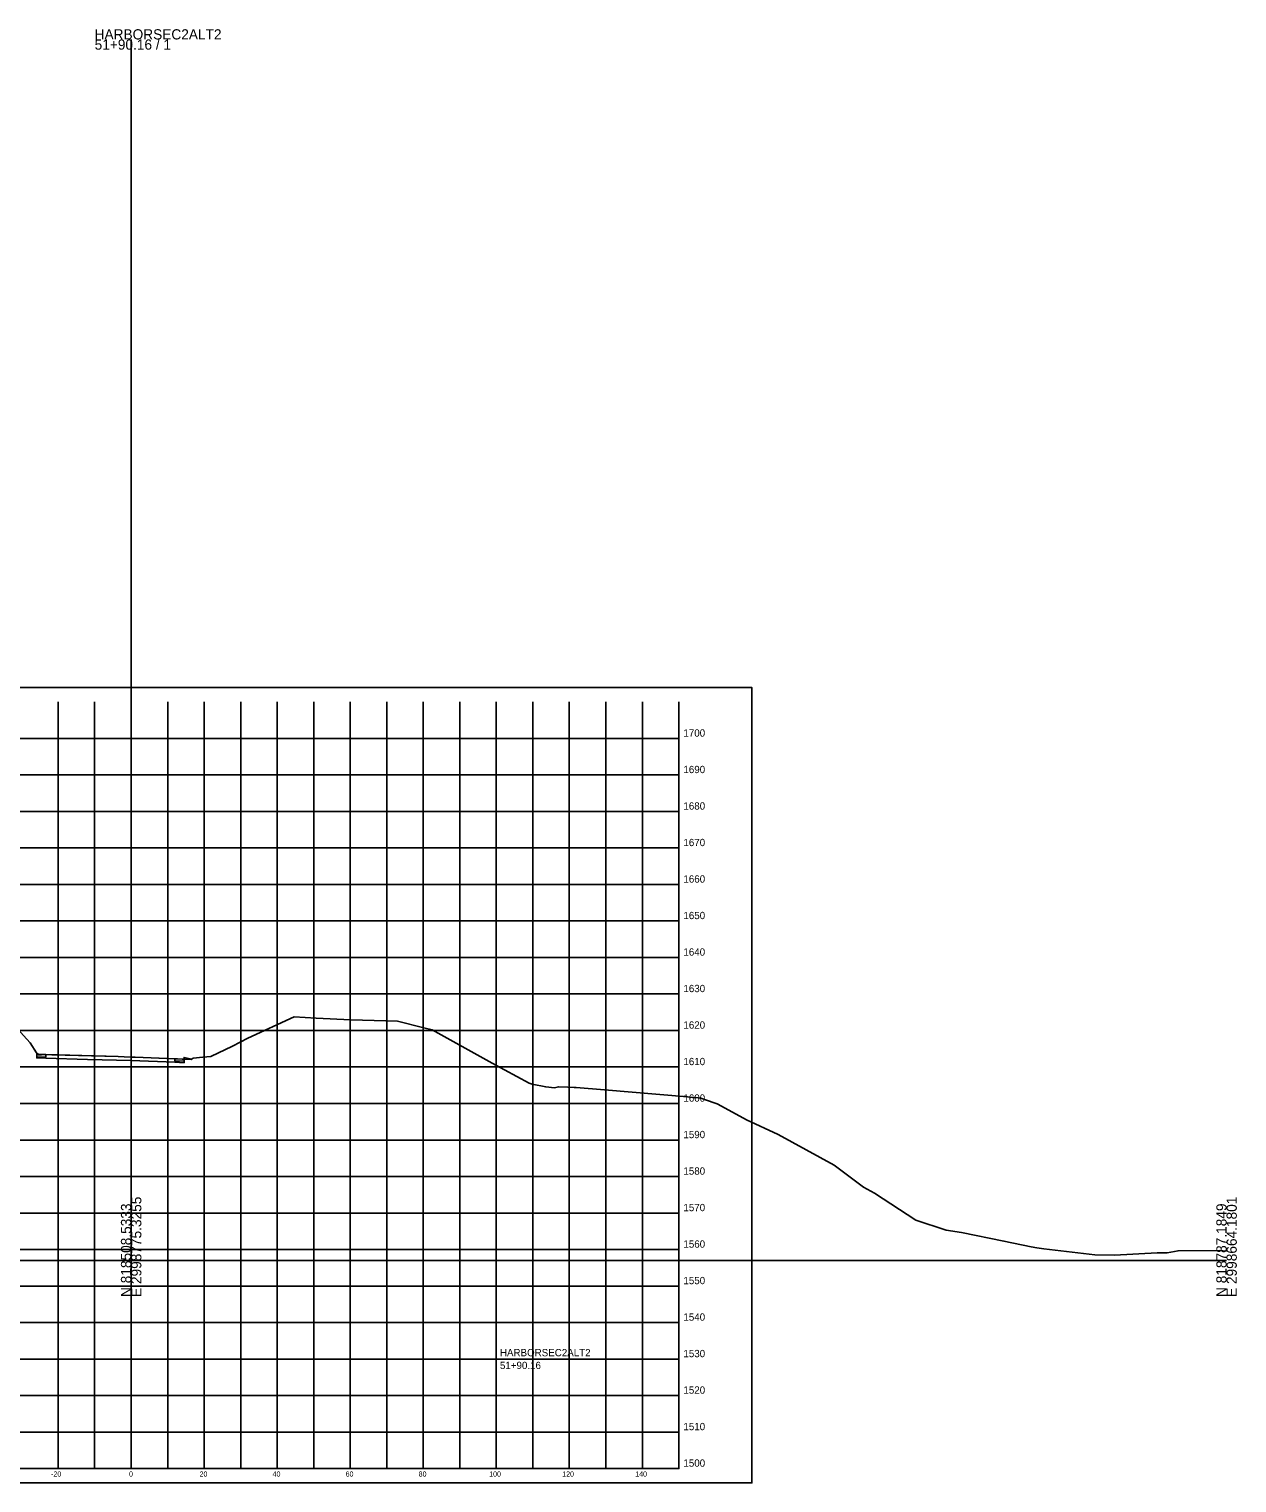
# Model space of a CAD drawing. Extents: x -26 to 1067, y -71 to 1837.
# Drawn here: x 272 to 602.8, y 1439.1 to 1837.3 of the extents above; entities that cross this region are included whole.
import ezdxf

# ---------------------------------------------------------------- set-up
doc = ezdxf.new("R2010")
doc.units = 0
for name, color, linetype in [('DESIGN - EARTHWORK - Shapes', 7, 'Continuous'), ('DESIGN - SHEET - Corner Text', 7, 'Continuous'), ('DESIGN - SHEET - Light Grid', 7, 'Continuous'), ('DESIGN - SHEET - Linework', 7, 'Continuous'), ('DESIGN - SHEET - Plot Shape', 7, 'Continuous'), ('DESIGN - TYPICAL - Warning Text', 7, 'Continuous'), ('SURVEY - GROUND - Top of Ground', 7, 'Continuous')]:
    doc.layers.add(name, color=color, linetype=linetype)

msp = doc.modelspace()

# ---------------------------------------------------------------- linework, layer by layer
at = {"layer": 'DESIGN - EARTHWORK - Shapes'}
for points in [[(274.16, 1556.74), (274.09, 1556.92), (274.3, 1556.73)], [(274.16, 1556.74), (274.09, 1556.92), (274.3, 1556.73)], [(274.66, 1556.24), (274.65, 1556.43), (274.63, 1556.43), (274.3, 1556.73), (274.16, 1556.74), (274.16, 1555.73), (276.66, 1555.78), (276.66, 1556.38), (276.36, 1556.38)], [(274.66, 1556.24), (274.65, 1556.43), (274.63, 1556.43), (274.3, 1556.73), (274.16, 1556.74), (274.16, 1555.73), (276.66, 1555.78), (276.66, 1556.38), (276.36, 1556.38)], [(300, 1554.75), (288, 1555.09), (276.66, 1555.41), (274.16, 1555.48), (274.16, 1555.73), (276.66, 1555.78), (276.66, 1556.38), (296.43, 1555.84), (298.1, 1555.79), (300, 1555.71), (301.07, 1555.67), (312, 1555.25), (312, 1554.65), (314.5, 1554.6), (314.5, 1554.18), (312, 1554.28)], [(300, 1554.75), (288, 1555.09), (276.66, 1555.41), (274.16, 1555.48), (274.16, 1555.73), (276.66, 1555.78), (276.66, 1556.38), (296.43, 1555.84), (298.1, 1555.79), (300, 1555.71), (301.07, 1555.67), (312, 1555.25), (312, 1554.65), (314.5, 1554.6), (314.5, 1554.18), (312, 1554.28)], [(274.66, 1556.24), (274.65, 1556.43), (276.36, 1556.38)], [(274.66, 1556.24), (274.65, 1556.43), (276.36, 1556.38)], [(314, 1555.11), (314, 1555.17), (314.5, 1555.15), (314.5, 1554.6), (312, 1554.65), (312, 1555.25), (312.73, 1555.22)], [(314, 1555.11), (314, 1555.17), (314.5, 1555.15), (314.5, 1554.6), (312, 1554.65), (312, 1555.25), (312.73, 1555.22)], [(314, 1555.11), (314, 1555.17), (312.73, 1555.22)], [(314, 1555.11), (314, 1555.17), (312.73, 1555.22)], [(316.47, 1555.07), (316.52, 1555.1), (314.5, 1555.61), (314.5, 1555.15)], [(316.47, 1555.07), (316.52, 1555.1), (314.5, 1555.61), (314.5, 1555.15)]]:
    msp.add_lwpolyline(points, close=True, dxfattribs=at)
at = {"layer": 'DESIGN - SHEET - Light Grid'}
for p, q in [((300, 1500), (300, 1834.48)), ((0, 1500), (300, 1500)), ((300, 1500), (600, 1500))]:
    msp.add_line(p, q, dxfattribs=at)
at = {"layer": 'DESIGN - SHEET - Linework'}
for p, q in [((280, 1443), (280, 1653)), ((290, 1443), (290, 1653)), ((300, 1443), (300, 1653)), ((310, 1443), (310, 1653)), ((320, 1443), (320, 1653)), ((330, 1443), (330, 1653)), ((340, 1443), (340, 1653)), ((350, 1443), (350, 1653)), ((360, 1443), (360, 1653)), ((370, 1443), (370, 1653)), ((380, 1443), (380, 1653)), ((390, 1443), (390, 1653)), ((400, 1443), (400, 1653)), ((410, 1443), (410, 1653)), ((420, 1443), (420, 1653)), ((430, 1443), (430, 1653)), ((440, 1443), (440, 1653)), ((150, 1643), (450, 1643)), ((150, 1633), (450, 1633)), ((150, 1623), (450, 1623)), ((150, 1613), (450, 1613)), ((150, 1603), (450, 1603)), ((150, 1593), (450, 1593)), ((150, 1583), (450, 1583)), ((150, 1573), (450, 1573)), ((150, 1563), (450, 1563)), ((150, 1553), (450, 1553)), ((150, 1543), (450, 1543)), ((150, 1533), (450, 1533)), ((150, 1523), (450, 1523)), ((150, 1513), (450, 1513)), ((150, 1503), (450, 1503)), ((150, 1493), (450, 1493)), ((150, 1483), (450, 1483)), ((150, 1473), (450, 1473)), ((150, 1463), (450, 1463)), ((150, 1453), (450, 1453))]:
    msp.add_line(p, q, dxfattribs=at)
msp.add_lwpolyline([(150, 1653), (150, 1443), (450, 1443), (450, 1653)], dxfattribs=at)
at = {"layer": 'DESIGN - SHEET - Plot Shape'}
msp.add_lwpolyline([(130, 1656.94), (470, 1656.94), (470, 1439.06), (130, 1439.06)], close=True, dxfattribs=at)
at = {"layer": 'SURVEY - GROUND - Top of Ground'}
msp.add_lwpolyline([(255.36, 1578.26), (272.31, 1559.58), (274.09, 1556.92), (274.63, 1556.43), (296.43, 1555.84), (298.1, 1555.79), (300, 1555.71), (301.07, 1555.67), (316.47, 1555.07), (317.02, 1555.39), (319.59, 1555.66), (321.83, 1555.89), (327.71, 1558.69), (332, 1560.91), (344.65, 1566.77), (350.71, 1566.35), (360.16, 1565.96), (372.9, 1565.56), (380.12, 1563.73), (382.46, 1563.19), (398.86, 1554.04), (409.02, 1548.54), (409.85, 1548.29), (413.55, 1547.55), (415.92, 1547.25), (417.01, 1547.57), (419.57, 1547.43), (421.37, 1547.38), (421.9, 1547.38), (429.66, 1546.77), (452.41, 1544.83), (453.82, 1544.67), (454.44, 1544.62), (456.02, 1544.46), (459.63, 1543.21), (460.47, 1542.95), (466.74, 1539.49), (468.49, 1538.52), (477.16, 1534.49), (492.58, 1526.14), (500.6, 1520.07), (503.55, 1518.41), (514.88, 1511.06), (523.17, 1508.31), (527.39, 1507.62), (539.03, 1505.33), (546.53, 1503.71), (548.07, 1503.48), (549.95, 1503.2), (563.92, 1501.56), (569.29, 1501.43), (580.98, 1502.12), (583.73, 1502.06), (586.74, 1502.66), (597.94, 1502.71), (600, 1502.59)], dxfattribs=at)

# ---------------------------------------------------------------- texts
at = {"layer": 'DESIGN - SHEET - Corner Text'}
for s, height, p in [('1700', 2, (451.25, 1643.5)), ('1690', 2, (451.25, 1633.5)), ('1680', 2, (451.25, 1623.5)), ('1670', 2, (451.25, 1613.5)), ('1660', 2, (451.25, 1603.5)), ('1650', 2, (451.25, 1593.5)), ('1640', 2, (451.25, 1583.5)), ('1630', 2, (451.25, 1573.5)), ('1620', 2, (451.25, 1563.5)), ('1610', 2, (451.25, 1553.5)), ('1600', 2, (451.25, 1543.5)), ('1590', 2, (451.25, 1533.5)), ('1580', 2, (451.25, 1523.5)), ('1570', 2, (451.25, 1513.5)), ('1560', 2, (451.25, 1503.5)), ('1550', 2, (451.25, 1493.5)), ('1540', 2, (451.25, 1483.5)), ('1530', 2, (451.25, 1473.5)), ('1520', 2, (451.25, 1463.5)), ('1510', 2, (451.25, 1453.5)), ('-20', 1.4, (278.06, 1440.8)), ('0', 1.4, (299.42, 1440.8)), ('20', 1.4, (318.74, 1440.8)), ('40', 1.4, (338.74, 1440.8)), ('60', 1.4, (358.74, 1440.8)), ('80', 1.4, (378.74, 1440.8)), ('100', 1.4, (398.06, 1440.8)), ('120', 1.4, (418.06, 1440.8)), ('140', 1.4, (438.06, 1440.8)), ('1500', 2, (451.25, 1443.5))]:
    msp.add_text(s, height=height, dxfattribs=at).set_placement(p)
at = {"layer": 'DESIGN - SHEET - Light Grid'}
for s, p in [('HARBORSEC2ALT2', (290, 1834.48)), ('51+90.16 / 1', (290, 1831.68))]:
    msp.add_text(s, height=2.8, dxfattribs=at).set_placement(p)
for s, p in [('N 818508.5333', (300, 1490)), ('E 2998775.3255', (302.8, 1490)), ('N 818787.1849', (600, 1490)), ('E 2998664.1801', (602.8, 1490))]:
    msp.add_text(s, height=2.8, rotation=90, dxfattribs=at).set_placement(p)
at = {"layer": 'DESIGN - TYPICAL - Warning Text'}
for s, p in [('HARBORSEC2ALT2', (401, 1473.75)), ('51+90.16', (401, 1470.25))]:
    msp.add_text(s, height=2, dxfattribs=at).set_placement(p)

doc.saveas('drawing.dxf')
